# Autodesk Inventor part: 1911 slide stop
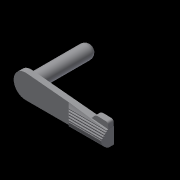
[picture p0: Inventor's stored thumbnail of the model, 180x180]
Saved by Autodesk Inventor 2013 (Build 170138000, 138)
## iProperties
Created: 2013-02
Part Number: 1911 slide stop
Material: Generic
Document SubType Name: Modeling
Designer: John
Density: 1 g/cm^3
Author: John
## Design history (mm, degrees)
sketch "Sketch1"
  geometry: L1 (0, 0)-(-30.328, 0); L2 (0, 5.838)-(-29.909, 8.717); L3 (0, 0)-(0, 5.838); A1 r 4.369 centre (-30.328, 4.369) between (-29.909, 8.717) and (-30.328, 0)
  constraints: 6 end point, 2 point on circle, 1 centre point, 1 horizontal, 1 tangent
extrude "Extrusion1" new body sketch "Sketch1" distance "d3" = 2.0574; taper "d4" = 0 deg
sketch "Sketch2"
  geometry: L1 (-2.057, 0)-(-2.057, 5.838) reference; L2 (0, 0)-(-11.33, 0); L3 (-2.057, 5.838)-(-2.057, 7.147) reference; A1 r 7.62 centre (-9.16, 9.906) between (-4.835, 3.632) and (-2.057, 7.147); A2 r 5.08 centre (0.157, 4.572) between (-4.835, 3.632) and (-2.057, 0)
  constraints: 4 end point, 4 point on circle, 2 centre point, 1 vertical, 1 other
extrude "Extrusion2" join sketch "Sketch2" distance "d14" = 24.9301; taper "d15" = 0 deg
sketch "Sketch4"
  geometry: L1 (5.398, 2.057)-(30.328, 2.057) reference; L2 (0, 2.057)-(5.398, 2.057) reference; L3 (30.328, 4.835)-(5.398, 4.835) reference; L4 (30.328, 4.835)-(18.644, 4.835); L5 (18.644, 4.835)-(15.866, 2.057); L6 (15.866, 2.057)-(3.261, 2.057); L7 (3.261, 2.057)-(3.261, 4.835); L8 (3.261, 4.835)-(5.398, 4.835)
  constraints: 10 end point, 3 point on line, 2 perpendicular
  dimensions: "d16" = 11.684 distance of L3.start L4.end; "d17" = 135 deg angle of L5 L4
extrude "Extrusion3" cut sketch "Sketch4" stored distance "d18" = 24.9301; taper "d19" = 0 deg
sketch "Sketch5"
  geometry: L1 (29.909, 8.717)-(0, 5.838) reference; L2 (0, 5.838)-(0, 0) reference; L3 (0, 5.838)-(0, 8.717); L4 (0, 8.717)-(15.856, 7.364)
  constraints: 4 end point, 1 collinear, 1 point on line
extrude "Extrusion4" cut sketch "Sketch5" distance "d20" = 24.9301; taper "d21" = 0 deg
sketch "Sketch6"
  geometry: C1 r 2.476 at (30.328, 4.369); A1 r 4.369 centre (30.328, 4.369) between (30.328, 0) and (29.909, 8.717) reference
  constraints: 1 centre point, 1 coincident
  dimensions: "d22" = 4.953 diameter of C1
extrude "Extrusion5" join sketch "Sketch6" distance "d23" = 22.0218; taper "d24" = 0 deg
sketch "Sketch8"
  geometry: L1 (-2.717, 5.838)-(-2.522, 5.439); L2 (-2.522, 5.439)-(-9.16, 9.906); L3 (-2.522, 5.439)-(-2.965, 5.47); L4 (-2.929, 4.887)-(-9.16, 9.906) reference; L5 (-2.929, 4.887)-(-3.089, 5.301); L6 (-2.929, 4.887)-(-3.368, 4.955); L7 (-2.929, 4.887)-(-3.368, 4.955); L8 (-3.089, 5.301)-(-2.929, 4.887); L9 (-3.382, 4.372)-(-3.813, 4.477) reference; L10 (-3.506, 4.798)-(-3.382, 4.372) reference; L11 (-3.877, 3.897)-(-4.297, 4.039) reference; L12 (-3.964, 4.332)-(-3.877, 3.897) reference; L13 (-4.411, 3.467)-(-4.818, 3.645) reference; L14 (-4.461, 3.908)-(-4.411, 3.467) reference; A1 r 8.001 centre (-9.16, 9.906) between (-2.522, 5.439) and (-2.929, 4.887) reference; 2 further points
  constraints: 28 end point, 5 point on circle, 1 centre point, 1 coincident, 18 other
  dimensions: "d35" = 30 deg angle of L2 L1; "d36" = 30 deg angle of L2 L3; "d38" = 30 deg angle of L4 L5; "d39" = 30 deg angle of L6 L4
extrude "Extrusion6" cut sketch "Sketch8" stored distance "d43" = 25.4; taper "d44" = 0 deg
sketch "Sketch9"
  geometry: L1 (29.909, 8.717)-(0, 5.838) reference; L2 (3.731, 8.085)-(0.848, 8.01); L3 (0.082, 7.257)-(0.027, 6.011); L4 (0, 5.838)-(6.186, 6.433); A1 r 2.388 centre (7.472, 8.445) between (5.456, 7.166) and (6.186, 6.433); A2 r 1.981 centre (3.783, 6.105) between (5.456, 7.166) and (3.731, 8.085); A3 r 0.787 centre (0.868, 7.223) between (0.848, 8.01) and (0.082, 7.257); A4 r 0.787 centre (-0.76, 6.045) between (0, 5.838) and (0.027, 6.011)
  constraints: 8 point on circle, 6 end point, 4 centre point, 1 collinear
extrude "Extrusion7" join sketch "Sketch9" distance "d45" = 2.032; taper "d46" = 0 deg
fillet "Fillet2" dims "d48" = 2.286
body "Solid1"
